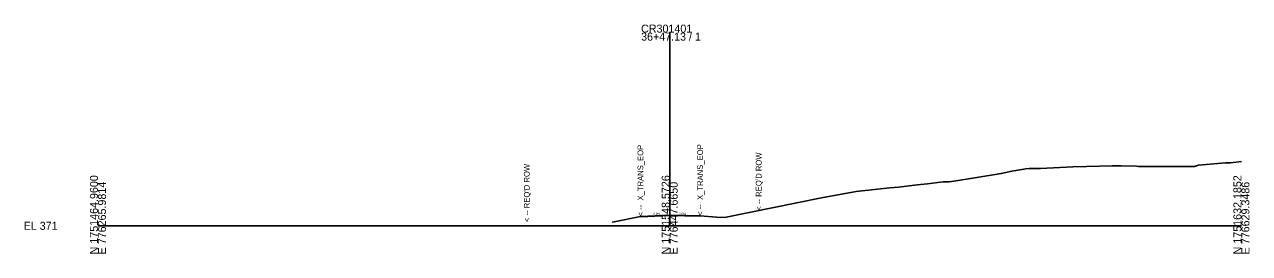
# Model space of a CAD drawing. Extents: x 765710 to 788731, y 1743078 to 1754528.
# Drawn here: x 788302.9 to 788731.5, y 1748452.4 to 1748532.5 of the extents above; entities that cross this region are included whole.
import ezdxf

# ---------------------------------------------------------------- set-up
doc = ezdxf.new("R2010")
doc.units = 0
for name, color, linetype in [('ControlPoints', 7, 'Continuous'), ('Level 1', 7, 'Continuous'), ('Setups', 7, 'Continuous'), ('SHEET_BORDER', 7, 'Continuous'), ('SHEET_WORK_NUMBER', 7, 'Continuous'), ('TS_X_GROUND', 7, 'Continuous')]:
    doc.layers.add(name, color=color, linetype=linetype)

msp = doc.modelspace()

# ---------------------------------------------------------------- linework, layer by layer
at = {"layer": 'ControlPoints'}
msp.add_lwpolyline([(788508.52, 1748463.42), (788509.21, 1748463.5), (788518.4, 1748465.39), (788528.59, 1748465.77), (788539.27, 1748465.57), (788545, 1748465.17), (788547.77, 1748464.98), (788581.81, 1748471.88), (788593.88, 1748474.07), (788601.37, 1748474.86), (788605.65, 1748475.39), (788608.69, 1748475.65), (788614.26, 1748476.27), (788616.43, 1748476.52), (788618.86, 1748476.8), (788624.26, 1748477.48), (788626.46, 1748477.52), (788628.03, 1748477.75), (788635.37, 1748478.9), (788644.65, 1748480.38), (788648.39, 1748481.23), (788653.26, 1748481.99), (788654.44, 1748482.12), (788657.35, 1748482.12), (788658.31, 1748482.16), (788669.65, 1748482.71), (788674.5, 1748482.88), (788683.44, 1748483.02), (788684.3, 1748483.02), (788686.62, 1748483.05), (788691.97, 1748482.94), (788692.68, 1748482.83), (788696.63, 1748482.85), (788698.39, 1748482.83), (788700.61, 1748482.84), (788707.16, 1748482.89), (788712.23, 1748482.86), (788713.59, 1748483.31), (788723.11, 1748484.1), (788724.82, 1748484.16), (788728.64, 1748484.62)], dxfattribs=at)
at = {"layer": 'Setups'}
for p, q in [((788528.64, 1748462.1), (788528.64, 1748529.67)), ((788328.64, 1748462.1), (788528.64, 1748462.1)), ((788528.64, 1748462.1), (788728.64, 1748462.1))]:
    msp.add_line(p, q, dxfattribs=at)
at = {"layer": 'SHEET_WORK_NUMBER'}
for p, q in [((788518.4, 1748465.39), (788518.41, 1748465.26)), ((788539.28, 1748465.45), (788539.28, 1748465.57))]:
    msp.add_line(p, q, dxfattribs=at)
for points in [[(788518.4, 1748465.39), (788528.59, 1748465.77), (788539.28, 1748465.57)], [(788518.41, 1748465.26), (788528.59, 1748465.65), (788539.28, 1748465.45)]]:
    msp.add_lwpolyline(points, dxfattribs=at)

# ---------------------------------------------------------------- texts
at = {"layer": 'Level 1'}
for p in [(788560.78, 1748467.41), (788479.64, 1748463.42)]:
    msp.add_text("< -- REQ'D ROW", height=2, rotation=90, dxfattribs=at).set_placement(p)
at = {"layer": 'Setups'}
for s, p in [('36+47.13 / 1', (788518.64, 1748526.87)), ('CR301401', (788518.64, 1748529.67)), ('EL 371', (788302.64, 1748460.7))]:
    msp.add_text(s, height=2.8, dxfattribs=at).set_placement(p)
for s, p in [('N 1751464.9600', (788328.64, 1748452.1)), ('E 776265.9814', (788331.44, 1748452.1)), ('N 1751548.5726', (788528.64, 1748452.1)), ('E 776447.6650', (788531.44, 1748452.1)), ('N 1751632.1852', (788728.64, 1748452.1)), ('E 776629.3486', (788731.44, 1748452.1))]:
    msp.add_text(s, height=2.8, rotation=90, dxfattribs=at).set_placement(p)
at = {"layer": 'SHEET_BORDER'}
for rotation, p in [(1.1458, (788522.86, 1748465.86)), (358.8542, (788531.87, 1748465.91))]:
    msp.add_text('2.0%', height=0.8, rotation=rotation, dxfattribs=at).set_placement(p)
at = {"layer": 'TS_X_GROUND'}
for p in [(788519.4, 1748465.39), (788540.27, 1748465.57)]:
    msp.add_text('< --  X_TRANS_EOP', height=2, rotation=90, dxfattribs=at).set_placement(p)

doc.saveas('drawing.dxf')
